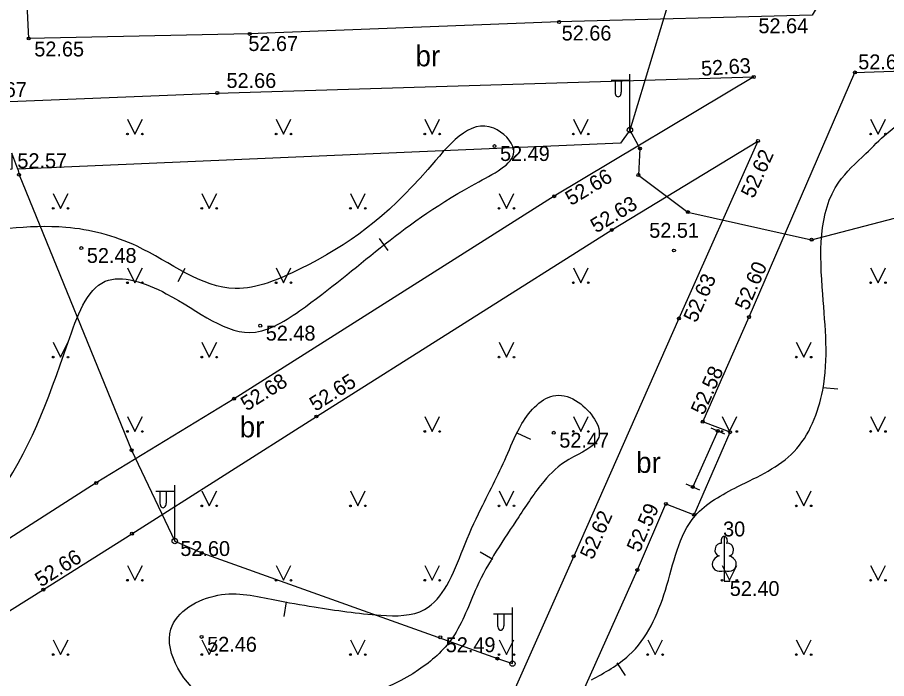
# Model space of a CAD drawing. Extents: x 619806 to 620082, y 405176 to 405386.
# Drawn here: x 619868.55 to 619897.79, y 405269.19 to 405291.42 of the extents above; entities that cross this region are included whole.
import ezdxf

# ---------------------------------------------------------------- set-up
doc = ezdxf.new("R2010")
doc.units = 0
for name, color, linetype in [('APGS_ELEM_####_####_#', 7, 'Continuous'), ('APGS_VADP_ZSPR_####_#', 7, 'Continuous'), ('BUVE_SOLS_####_####_#', 7, 'Continuous'), ('CELI_CMAL_####_####_#', 7, 'Continuous'), ('CELI_CSEG_####_TKST_#', 7, 'Continuous'), ('RELJ_AATZ_####_TKST_#', 7, 'Continuous'), ('RELJ_ELEM_####_####_#', 7, 'Continuous'), ('RELJ_HORZ_PAMT_####_#', 7, 'Continuous'), ('TERT_DIAM_####_TKST_#', 7, 'Continuous'), ('TERT_ELEM_####_####_#', 7, 'Continuous')]:
    doc.layers.add(name, color=color, linetype=linetype)

msp = doc.modelspace()

# ---------------------------------------------------------------- linework, layer by layer
at = {"layer": 'APGS_ELEM_####_####_#'}
for p, q in [((619889.151, 405289.3), (619888.516, 405289.295)), ((619888.651, 405289.296), (619888.651, 405288.904)), ((619888.861, 405289.298), (619888.861, 405288.904)), ((619889.151, 405287.633), (619889.151, 405289.516)), ((619873.841, 405273.815), (619873.841, 405275.698)), ((619873.841, 405275.482), (619873.206, 405275.477)), ((619873.341, 405275.478), (619873.341, 405275.086)), ((619873.551, 405275.48), (619873.551, 405275.086)), ((619885.202, 405269.696), (619885.202, 405271.579)), ((619885.202, 405271.363), (619884.567, 405271.358)), ((619884.702, 405271.359), (619884.702, 405270.967)), ((619884.912, 405271.361), (619884.912, 405270.967))]:
    msp.add_line(p, q, dxfattribs=at)
for centre in [(619889.151, 405287.633), (619873.841, 405273.815), (619885.202, 405269.696)]:
    msp.add_circle(centre, 0.09, dxfattribs=at)
for centre in [(619888.756, 405288.904), (619873.446, 405275.086), (619884.807, 405270.967)]:
    msp.add_ellipse(centre, major_axis=(0, 0.151), ratio=0.695971, start_param=1.570796, end_param=4.712389, dxfattribs=at)
at = {"layer": 'APGS_VADP_ZSPR_####_#'}
for points in [[(619926.053, 405342.093), (619924.906, 405341.871), (619913.437, 405323.942), (619914.167, 405323.421), (619913.311, 405323.727), (619901.199, 405304.503), (619901.88, 405304.137), (619901.118, 405304.337), (619891.212, 405294.458), (619889.151, 405287.633)], [(619889.151, 405287.633), (619888.839, 405287.188), (619868.564, 405286.313), (619868.359, 405286.853), (619868.361, 405286.315), (619854.776, 405285.354), (619845.67, 405285.418), (619844.273, 405285.984), (619845.432, 405287.623), (619843.395, 405290.297), (619835.199, 405289.5), (619828.336, 405290.779), (619827.279, 405290.766)], [(619889.151, 405287.633), (619889.486, 405287.011), (619889.44, 405286.121), (619891.102, 405284.875), (619895.261, 405283.948), (619904.24, 405286.286), (619904.319, 405287.722), (619904.441, 405286.35), (619922.582, 405287.176), (619922.83, 405287.786), (619922.954, 405287.209), (619932.902, 405287.177), (619938.46, 405286.492), (619942.211, 405287.557), (619942.781, 405287.929)], [(619868.564, 405286.313), (619868.601, 405286.13), (619872.388, 405276.869), (619873.841, 405273.815), (619874.747, 405273.418), (619884.696, 405269.866), (619885.202, 405269.696)]]:
    msp.add_lwpolyline(points, dxfattribs=at)
at = {"layer": 'BUVE_SOLS_####_####_#'}
for p, q in [((619891.876, 405277.62), (619892.333, 405277.417)), ((619892.105, 405277.519), (619891.266, 405275.638)), ((619891.038, 405275.74), (619891.494, 405275.536))]:
    msp.add_line(p, q, dxfattribs=at)
at = {"layer": 'CELI_CMAL_####_####_#'}
for points in [[(619901.141, 405301.297), (619895.285, 405291.495), (619886.767, 405291.266), (619876.357, 405290.867), (619868.929, 405290.713), (619868.879, 405291.869), (619865.764, 405291.699), (619865.807, 405290.556), (619863.458, 405290.505), (619853.554, 405290.137), (619841.43, 405289.76), (619840.169, 405289.507), (619836.17, 405288.32), (619833.502, 405287.788), (619826.905, 405297.999), (619827.372, 405299.068), (619837.906, 405304.107), (619846.534, 405308.229), (619856.914, 405313.201), (619868.255, 405318.592), (619880.738, 405324.67), (619889.516, 405328.858), (619904.867, 405336.211)], [(619899.158, 405249.84), (619889.566, 405255.126), (619883.763, 405258.374), (619883.521, 405258.553), (619883.337, 405258.79), (619883.332, 405259.088), (619883.396, 405259.355), (619885.336, 405263.687), (619885.909, 405265.039), (619889.402, 405272.847), (619890.363, 405275.067), (619891.31, 405274.7), (619892.522, 405277.476), (619891.601, 405277.83), (619893.159, 405281.35), (619896.721, 405289.572), (619907.468, 405289.939)], [(619836.706, 405284.543), (619837.518, 405286.469), (619840.363, 405287.459), (619841.354, 405287.676), (619853.093, 405288.124), (619867.164, 405288.545), (619875.272, 405288.879), (619893.318, 405289.417), (619886.606, 405285.41), (619875.838, 405278.602), (619871.198, 405275.77), (619866.813, 405272.975), (619862.385, 405270.176), (619850.722, 405276.664), (619841.154, 405281.99), (619836.706, 405284.543)], [(619864.449, 405269.077), (619869.423, 405272.184), (619872.398, 405274.064), (619878.606, 405278.004), (619888.543, 405284.278), (619893.459, 405287.265), (619890.801, 405281.299), (619887.26, 405273.308), (619884.168, 405266.346), (619883.371, 405264.557), (619881.435, 405260.185), (619881.348, 405260.055), (619881.222, 405259.974), (619881.004, 405259.965), (619880.8, 405260.037), (619870.43, 405265.727), (619864.449, 405269.077)]]:
    msp.add_lwpolyline(points, dxfattribs=at)
at = {"layer": 'RELJ_ELEM_####_####_#'}
for centre in [(619886.767, 405291.266), (619868.929, 405290.713), (619876.357, 405290.867), (619896.721, 405289.572), (619893.318, 405289.417), (619875.272, 405288.879), (619893.459, 405287.265), (619884.596, 405287.094), (619889.486, 405287.011), (619868.601, 405286.13), (619889.44, 405286.121), (619886.606, 405285.41), (619891.102, 405284.875), (619888.543, 405284.278), (619895.261, 405283.948), (619870.696, 405283.666), (619890.634, 405283.584), (619893.159, 405281.35), (619876.715, 405281.057), (619890.801, 405281.299), (619875.838, 405278.602), (619878.606, 405278.004), (619891.601, 405277.83), (619886.591, 405277.457), (619892.105, 405277.519), (619892.522, 405277.476), (619872.388, 405276.869), (619871.198, 405275.77), (619891.266, 405275.638), (619890.363, 405275.067), (619891.31, 405274.7), (619872.398, 405274.064), (619874.747, 405273.418), (619887.26, 405273.308), (619889.402, 405272.847), (619869.423, 405272.184), (619874.743, 405270.596), (619882.77, 405270.581), (619884.696, 405269.866)]:
    msp.add_circle(centre, 0.05, dxfattribs=at)
at = {"layer": 'RELJ_HORZ_PAMT_####_#'}
for p, q in [((619880.718, 405283.987), (619881.007, 405283.579)), ((619873.96, 405282.543), (619874.19, 405282.987)), ((619896.143, 405278.922), (619895.645, 405278.969)), ((619885.814, 405277.228), (619885.361, 405277.44)), ((619884.113, 405273.457), (619884.544, 405273.203)), ((619877.517, 405271.276), (619877.604, 405271.769)), ((619888.999, 405269.299), (619888.726, 405269.718))]:
    msp.add_line(p, q, dxfattribs=at)
for points in [[(619887.855, 405269.148), (619889.12, 405269.976), (619890.345, 405272.168), (619891.345, 405274.665), (619892.785, 405275.65), (619894.673, 405276.824), (619895.637, 405278.889), (619895.637, 405282.116), (619896.178, 405285.879), (619897.087, 405286.842), (619898.566, 405288.02), (619902.05, 405287.072), (619905.151, 405285.41), (619906.813, 405285.589), (619908.935, 405287.464), (619909.163, 405286.902), (619908.582, 405283.331), (619907.046, 405271.1), (619905.455, 405265.372), (619902.979, 405260.677), (619900.798, 405257.889), (619898.289, 405258.38), (619891.711, 405260.242), (619887.92, 405262.299), (619887.202, 405264.358), (619886.645, 405266.658)], [(619862.12, 405283.56), (619866.347, 405284.072), (619870.176, 405284.36), (619872.57, 405283.726), (619875.877, 405282.305), (619878.056, 405282.964), (619882.355, 405286.311), (619884.573, 405287.696), (619885.242, 405286.98), (619884.066, 405285.895), (619878.235, 405281.695), (619876.552, 405280.844), (619873.556, 405282.133), (619871.504, 405282.549), (619870.25, 405280.5), (619867.776, 405275.169), (619866.854, 405274.292), (619864.131, 405274.836), (619862.108, 405272.722), (619860.734, 405271.784), (619858.644, 405272.772), (619855.468, 405275.204), (619851.943, 405277.991), (619850.454, 405281.625), (619851.371, 405282.722), (619855.287, 405283.69), (619860.401, 405283.354), (619862.12, 405283.56)], [(619878.532, 405271.605), (619880.771, 405271.323), (619882.247, 405271.52), (619882.991, 405272.32), (619883.537, 405273.557), (619884.142, 405274.903), (619885.045, 405276.769), (619885.515, 405277.763), (619886.662, 405278.715), (619887.416, 405278.486), (619888.101, 405277.299), (619887.1, 405276.561), (619886.257, 405275.822), (619885.414, 405274.635), (619883.998, 405272.265), (619883.18, 405270.562), (619882.039, 405269.482), (619878.598, 405268.161), (619876.372, 405267.937), (619873.942, 405269.545), (619873.71, 405270.859), (619875.289, 405271.996), (619877.208, 405271.838), (619878.532, 405271.606)]]:
    msp.add_spline(points, degree=3, dxfattribs=at)
at = {"layer": 'TERT_ELEM_####_####_#'}
for p, q in [((619872.25, 405288), (619872.5, 405287.5)), ((619872.5, 405287.5), (619872.75, 405288)), ((619877.25, 405288), (619877.5, 405287.5)), ((619877.5, 405287.5), (619877.75, 405288)), ((619882.25, 405288), (619882.5, 405287.5)), ((619882.5, 405287.5), (619882.75, 405288)), ((619887.25, 405288), (619887.5, 405287.5)), ((619887.5, 405287.5), (619887.75, 405288)), ((619897.25, 405288), (619897.5, 405287.5)), ((619897.5, 405287.5), (619897.75, 405288)), ((619869.75, 405285.5), (619870, 405285)), ((619870, 405285), (619870.25, 405285.5)), ((619874.75, 405285.5), (619875, 405285)), ((619875, 405285), (619875.25, 405285.5)), ((619879.75, 405285.5), (619880, 405285)), ((619880, 405285), (619880.25, 405285.5)), ((619884.75, 405285.5), (619885, 405285)), ((619885, 405285), (619885.25, 405285.5)), ((619872.25, 405283), (619872.5, 405282.5)), ((619872.5, 405282.5), (619872.75, 405283)), ((619877.25, 405283), (619877.5, 405282.5)), ((619877.5, 405282.5), (619877.75, 405283)), ((619887.25, 405283), (619887.5, 405282.5)), ((619887.5, 405282.5), (619887.75, 405283)), ((619897.25, 405283), (619897.5, 405282.5)), ((619897.5, 405282.5), (619897.75, 405283)), ((619869.75, 405280.5), (619870, 405280)), ((619870, 405280), (619870.25, 405280.5)), ((619874.75, 405280.5), (619875, 405280)), ((619875, 405280), (619875.25, 405280.5)), ((619884.75, 405280.5), (619885, 405280)), ((619885, 405280), (619885.25, 405280.5)), ((619894.75, 405280.5), (619895, 405280)), ((619895, 405280), (619895.25, 405280.5)), ((619872.25, 405278), (619872.5, 405277.5)), ((619872.5, 405277.5), (619872.75, 405278)), ((619882.25, 405278), (619882.5, 405277.5)), ((619882.5, 405277.5), (619882.75, 405278)), ((619887.25, 405278), (619887.5, 405277.5)), ((619887.5, 405277.5), (619887.75, 405278)), ((619892.25, 405278), (619892.5, 405277.5)), ((619892.5, 405277.5), (619892.75, 405278)), ((619897.25, 405278), (619897.5, 405277.5)), ((619897.5, 405277.5), (619897.75, 405278)), ((619874.75, 405275.5), (619875, 405275)), ((619875, 405275), (619875.25, 405275.5)), ((619879.75, 405275.5), (619880, 405275)), ((619880, 405275), (619880.25, 405275.5)), ((619884.75, 405275.5), (619885, 405275)), ((619885, 405275), (619885.25, 405275.5)), ((619894.75, 405275.5), (619895, 405275)), ((619895, 405275), (619895.25, 405275.5)), ((619872.25, 405273), (619872.5, 405272.5)), ((619872.5, 405272.5), (619872.75, 405273)), ((619877.25, 405273), (619877.5, 405272.5)), ((619877.5, 405272.5), (619877.75, 405273)), ((619882.25, 405273), (619882.5, 405272.5)), ((619882.5, 405272.5), (619882.75, 405273)), ((619892.25, 405273), (619892.5, 405272.5)), ((619892.5, 405272.5), (619892.75, 405273)), ((619897.25, 405273), (619897.5, 405272.5)), ((619897.5, 405272.5), (619897.75, 405273)), ((619892.325, 405272.819), (619892.325, 405272.472)), ((619892.325, 405272.472), (619892.525, 405272.472)), ((619869.75, 405270.5), (619870, 405270)), ((619870, 405270), (619870.25, 405270.5)), ((619874.75, 405270.5), (619875, 405270)), ((619875, 405270), (619875.25, 405270.5)), ((619879.75, 405270.5), (619880, 405270)), ((619880, 405270), (619880.25, 405270.5)), ((619884.75, 405270.5), (619885, 405270)), ((619885, 405270), (619885.25, 405270.5)), ((619889.75, 405270.5), (619890, 405270)), ((619890, 405270), (619890.25, 405270.5)), ((619894.75, 405270.5), (619895, 405270)), ((619895, 405270), (619895.25, 405270.5))]:
    msp.add_line(p, q, dxfattribs=at)
for points in [[(619892.325, 405273.972), (619892.325, 405272.819)], [(619892.415, 405273.74), (619892.414, 405273.741)]]:
    msp.add_lwpolyline(points, dxfattribs=at)
for centre, radius in [((619872.25, 405287.5), 0.028), ((619872.75, 405287.5), 0.0263), ((619877.25, 405287.5), 0.028), ((619877.75, 405287.5), 0.0263), ((619882.25, 405287.5), 0.028), ((619882.75, 405287.5), 0.0263), ((619887.25, 405287.5), 0.028), ((619887.75, 405287.5), 0.0263), ((619897.25, 405287.5), 0.028), ((619897.75, 405287.5), 0.0263), ((619869.75, 405285), 0.028), ((619870.25, 405285), 0.0263), ((619874.75, 405285), 0.028), ((619875.25, 405285), 0.0263), ((619879.75, 405285), 0.028), ((619880.25, 405285), 0.0263), ((619884.75, 405285), 0.028), ((619885.25, 405285), 0.0263), ((619872.25, 405282.5), 0.028), ((619872.75, 405282.5), 0.0263), ((619877.25, 405282.5), 0.028), ((619877.75, 405282.5), 0.0263), ((619887.25, 405282.5), 0.028), ((619887.75, 405282.5), 0.0263), ((619897.25, 405282.5), 0.028), ((619897.75, 405282.5), 0.0263), ((619869.75, 405280), 0.028), ((619870.25, 405280), 0.0263), ((619874.75, 405280), 0.028), ((619875.25, 405280), 0.0263), ((619884.75, 405280), 0.028), ((619885.25, 405280), 0.0263), ((619894.75, 405280), 0.028), ((619895.25, 405280), 0.0263), ((619872.25, 405277.5), 0.028), ((619872.75, 405277.5), 0.0263), ((619882.25, 405277.5), 0.028), ((619882.75, 405277.5), 0.0263), ((619887.25, 405277.5), 0.028), ((619887.75, 405277.5), 0.0263), ((619892.25, 405277.5), 0.028), ((619892.75, 405277.5), 0.0263), ((619897.25, 405277.5), 0.028), ((619897.75, 405277.5), 0.0263), ((619874.75, 405275), 0.028), ((619875.25, 405275), 0.0263), ((619879.75, 405275), 0.028), ((619880.25, 405275), 0.0263), ((619884.75, 405275), 0.028), ((619885.25, 405275), 0.0263), ((619894.75, 405275), 0.028), ((619895.25, 405275), 0.0263), ((619872.25, 405272.5), 0.028), ((619872.75, 405272.5), 0.0263), ((619877.25, 405272.5), 0.028), ((619877.75, 405272.5), 0.0263), ((619882.25, 405272.5), 0.028), ((619882.75, 405272.5), 0.0263), ((619892.25, 405272.5), 0.028), ((619892.75, 405272.5), 0.0263), ((619897.25, 405272.5), 0.028), ((619897.75, 405272.5), 0.0263), ((619869.75, 405270), 0.028), ((619870.25, 405270), 0.0263), ((619874.75, 405270), 0.028), ((619875.25, 405270), 0.0263), ((619879.75, 405270), 0.028), ((619880.25, 405270), 0.0263), ((619884.75, 405270), 0.028), ((619885.25, 405270), 0.0263), ((619889.75, 405270), 0.028), ((619890.25, 405270), 0.0263), ((619894.75, 405270), 0.028), ((619895.25, 405270), 0.0263)]:
    msp.add_circle(centre, radius, dxfattribs=at)
for centre, major_axis, ratio, start_param, end_param in [((619892.325, 405273.822), (0, -0.15), 0.707107, 3.14537, 5.287485), ((619892.325, 405273.822), (0, -0.15), 0.707107, 0.995701, 3.137816), ((619892.197, 405273.527), (-0.039, -0.212), 0.861323, 3.141593, 6.283185), ((619892.453, 405273.527), (0.039, -0.212), 0.861323, 0, 3.141593), ((619892.235, 405273.065), (0.307, 0.095), 0.814445, 1.570796, 4.752015), ((619892.415, 405273.065), (-0.307, 0.095), 0.814445, 1.531171, 4.712389)]:
    msp.add_ellipse(centre, major_axis=major_axis, ratio=ratio, start_param=start_param, end_param=end_param, dxfattribs=at)

# ---------------------------------------------------------------- texts
at = {"layer": 'CELI_CSEG_####_TKST_#'}
for p in [(619881.938, 405289.776), (619876.024, 405277.304), (619889.361, 405276.109)]:
    msp.add_text('br', height=0.7, dxfattribs=at).set_placement(p)
at = {"layer": 'RELJ_AATZ_####_TKST_#'}
for s, p in [(' 52.64', (619893.289, 405290.889)), (' 52.66', (619886.67, 405290.644)), (' 52.67', (619876.13, 405290.291)), (' 52.65', (619868.929, 405290.108)), (' 52.62', (619896.647, 405289.676)), (' 52.66', (619875.394, 405289.049)), (' 52.67', (619867.004, 405288.744)), (' 52.49', (619884.596, 405286.594)), (' 52.57', (619868.359, 405286.353)), (' 52.51', (619889.616, 405284.013)), (' 52.48', (619870.696, 405283.166)), (' 52.48', (619876.715, 405280.557)), (' 52.47', (619886.591, 405276.957)), (' 52.60', (619873.841, 405273.315)), (' 52.40', (619892.325, 405271.972)), (' 52.46', (619874.743, 405270.096)), (' 52.49', (619882.77, 405270.081))]:
    msp.add_text(s, height=0.5, dxfattribs=at).set_placement(p)
for s, rotation, p in [(' 52.63', 3.6958, (619891.376, 405289.44)), (' 52.62', 65.6611, (619893.238, 405285.14)), (' 52.66', 30.8368, (619887.01, 405284.981)), (' 52.63', 31.2832, (619887.86, 405284.057)), (' 52.60', 66.5764, (619893.041, 405281.366)), (' 52.63', 65.9858, (619891.308, 405280.961)), (' 52.58', 66.1252, (619891.558, 405277.856)), (' 52.68', 32.3029, (619876.105, 405278.069)), (' 52.65', 32.2674, (619878.416, 405278.06)), (' 52.59', 66.593, (619889.404, 405273.238)), (' 52.62', 66.1007, (619887.828, 405272.995)), (' 52.66', 32.2901, (619869.181, 405272.153))]:
    msp.add_text(s, height=0.5, rotation=rotation, dxfattribs=at).set_placement(p)
at = {"layer": 'TERT_DIAM_####_TKST_#'}
msp.add_text(' 30', height=0.5, dxfattribs=at).set_placement((619892.1, 405273.972))

doc.saveas('drawing.dxf')
